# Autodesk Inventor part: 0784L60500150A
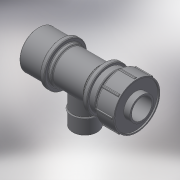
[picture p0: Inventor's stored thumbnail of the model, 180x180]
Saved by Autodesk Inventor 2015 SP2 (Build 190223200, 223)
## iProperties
Created: 2018-02
Part Number: 0784L60500150A
Material: Generic
Description: PLASSON MODULAR MALE TEE 50-1.1/2"-50
Document SubType Name: Modeling
Designer: KIM
Density: 1 g/cm^3
Appearance: Default
Author: KIM
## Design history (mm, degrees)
derived "0784L6.ipt"
feature "Solid1::0784L6.ipt"
feature "Solid2::0784L6.ipt"
tag "TaggingFeature1"
body "Solid1"
other parameters: "d26" = 38.55665, "d51" = 2, "d52" = 4.8, "d54" = 0, "d55" = 2, "d56" = 1, "d58" = 360 deg, "d60" = 1, "d63" = 1, "d65" = 0, "d67" = 0, "d69" = 183, "d70" = 77, "d71" = 47.803, "d73" = 93.12, "d74" = 75, "d75" = 35, "d76" = 88.32, "d77" = 41, "d79" = 46.5, "d80" = 42.5, "d82" = 7, "d83" = 86.4, "d84" = 86.4, "d86" = 72, "d88" = 76.8, "d89" = 67.2, "d90" = 10.25, "d91" = 38.95, "d92" = 81.6, "d93" = 45.1, "d94" = 36.9, "d95" = 8.2, "d96" = 55.35, "d97" = 54.9, "d98" = 67.2, "d99" = 48, "d100" = 43.2, "d101" = 22, "d102" = 35.85225, "d103" = 52.5833, "d104" = 24.2, "E_" = 96, "H_" = 183, "l_1" = 41, "l_2" = 22, "A_" = 77, "d_" = 1, "R_" = 47.803, "ODP_" = 75, "LPT_" = 35
